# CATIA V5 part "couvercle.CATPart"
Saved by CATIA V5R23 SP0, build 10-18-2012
Part number: couvercle
Definition: couvercle
Source: made
Bounding box of the stored display mesh (mm): x -44 to 44, y -115 to -15, z -12 to 16
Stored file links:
  C:\wamp\www\COURS\CONCEPTION GMP1\TITRE 01-CATIA VOLUMIQUE\05--ACTIONNEUR DE VANNE\prof\CORRECTION\Assemblage\couvercle.CATPart
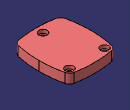
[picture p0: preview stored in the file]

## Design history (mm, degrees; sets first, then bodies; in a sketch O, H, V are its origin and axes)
Body1 "NONE" (main body)
  Solid1 "Manifold Solid #8428": solid without history
  Sketch1 "Esquisse.1" on face of Solid1, origin (0, 0, 16), H (1, 0, 0), V (0, 1, 0)
    projected arc E1 centre (29.844, -27.6401) radius 4.2 from (34.044, -27.6401) to (25.644, -27.6401) ccw from edge [face of Solid1 | face of Solid1]
    projected arc E2 centre (29.844, -27.6401) radius 4.2 from (25.644, -27.6401) to (34.044, -27.6401) ccw from edge [face of Solid1 | face of Solid1]
    projected arc E3 centre (-29.844, -27.6401) radius 4.2 from (-34.044, -27.6401) to (-25.644, -27.6401) ccw from edge [face of Solid1 | face of Solid1]
    projected arc E4 centre (-29.844, -27.6401) radius 4.2 from (-25.644, -27.6401) to (-34.044, -27.6401) ccw from edge [face of Solid1 | face of Solid1]
    projected arc E5 centre (-29.844, -102.3599) radius 4.2 from (-25.644, -102.3599) to (-34.044, -102.3599) ccw from edge [face of Solid1 | face of Solid1]
    projected arc E6 centre (-29.844, -102.3599) radius 4.2 from (-34.044, -102.3599) to (-25.644, -102.3599) ccw from edge [face of Solid1 | face of Solid1]
    projected arc E7 centre (29.844, -102.3599) radius 4.2 from (25.644, -102.3599) to (34.044, -102.3599) ccw from edge [face of Solid1 | face of Solid1]
    projected arc E8 centre (29.844, -102.3599) radius 4.2 from (34.044, -102.3599) to (25.644, -102.3599) ccw from edge [face of Solid1 | face of Solid1]
  Pad1: profile Sketch1, direction (0, 0, -1), up to face of Solid1
  Sketch2 "Esquisse.2" on face of Solid1, origin (30.6233, -32.9741, 16), H (1, 0, 0), V (0, 1, 0)
    point P1 (-0.7792, 5.334)
    reference projected arc E1 centre (-0.7792, 5.334) radius 10 from (8.9763, 7.5317) to (0.9763, 15.1787) ccw from edge [face of Solid1 | face of Solid1]
    concentricity: P1 E1
  Hole1: placed by Sketch2, at (29.844, -27.6401, 16) direction (0, 0, -1), diameter 8.5, through (limit type 6), counterbore diameter 14, counterbore depth 6
  Sketch3 "Esquisse.3" on face of Solid1, origin (0, 0, 16), H (1, 0, 0), V (0, 1, 0)
    point P1 (0, -102.3599)
    point P2 (-29.844, -27.6401)
    reference projected arc E1 centre (-29.844, -27.6401) radius 10 from (-31.5995, -17.7954) to (-39.5995, -25.4425) ccw from edge [face of Solid1 | face of Solid1]
    distance H P1 = 102.3599
    concentricity: P2 E1
    coincidence: V P1
  UserPattern1: of Hole1, copies 3, at the points of Sketch3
